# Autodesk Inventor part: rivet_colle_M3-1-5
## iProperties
Created: 2011-01
Part Number: rivet_colle_M3-1-5
Document SubType Name: Modeling
Designer: eric
Density: 1 g/cm^3
Mass: 0.0582176 g
Surface Area: 1.30769 cm^2
Volume: 0.0582176 cm^3
Author: eric
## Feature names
1. Base1
